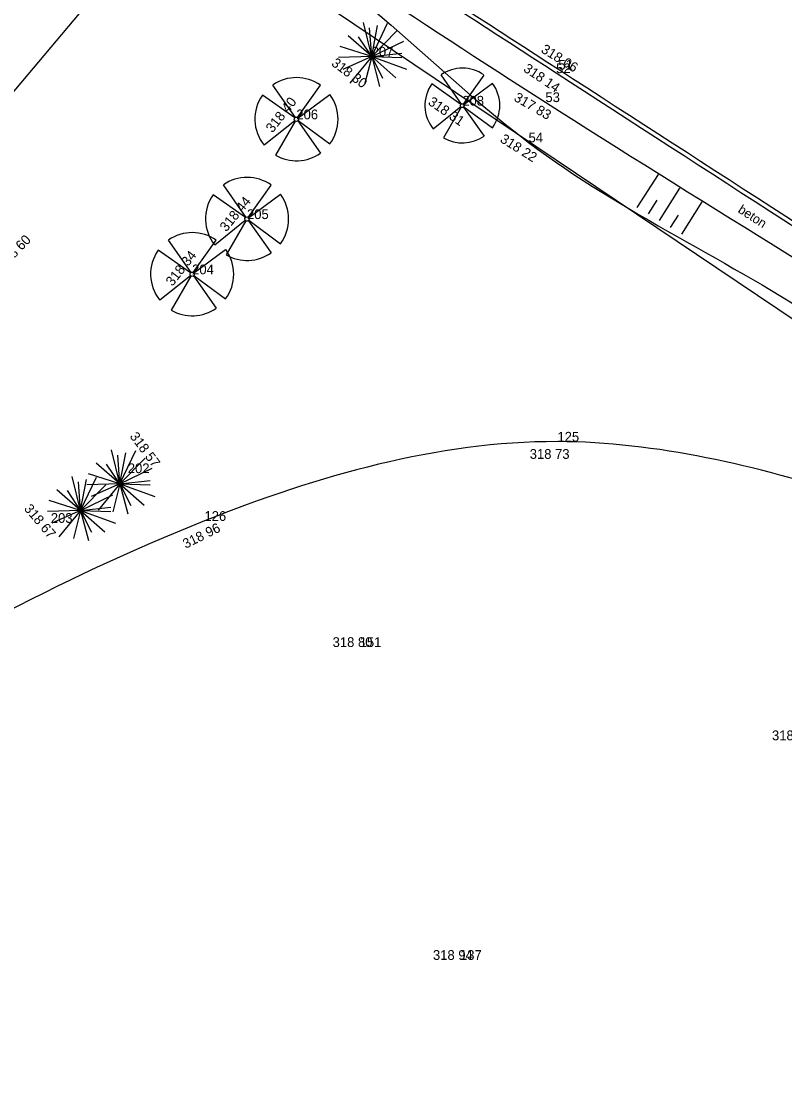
# Model space of a CAD drawing. Extents: x -742884 to -742543, y -1054677 to -1054433.
# Drawn here: x -742729.63 to -742706.11, y -1054520.62 to -1054488.13 of the extents above; entities that cross this region are included whole.
import ezdxf

# ---------------------------------------------------------------- set-up
doc = ezdxf.new("R2010")
doc.units = 0
for name, color, linetype in [('Vrstva 1', 7, 'Continuous'), ('Vrstva 10', 7, 'Continuous'), ('Vrstva 11', 7, 'Continuous'), ('Vrstva 13', 7, 'Continuous'), ('Vrstva 15', 7, 'Continuous'), ('Vrstva 2', 7, 'Continuous'), ('Vrstva 3', 7, 'Continuous'), ('Vrstva 4', 7, 'Continuous'), ('Vrstva 50', 7, 'Continuous')]:
    doc.layers.add(name, color=color, linetype=linetype)

# ---------------------------------------------------------------- blocks, each defined once
blk = doc.blocks.new('Z15')
at = {"layer": 'Vrstva 2'}
for p, q in [((-10, 2), (-8, 6)), ((-10, -2), (-10, 2)), ((-8, 6), (-6, 8)), ((-6, 8), (-2, 10)), ((-2, 10), (2, 10)), ((2, 10), (6, 8)), ((6, 8), (8, 6)), ((8, 6), (10, 2)), ((10, 2), (10, -2)), ((-8, -6), (-10, -2)), ((-6, -8), (-8, -6)), ((-2, -10), (-6, -8)), ((2, -10), (-2, -10)), ((6, -8), (2, -10)), ((8, -6), (6, -8)), ((10, -2), (8, -6))]:
    blk.add_line(p, q, dxfattribs=at)

msp = doc.modelspace()

# ---------------------------------------------------------------- linework, layer by layer
at = {"layer": 'Vrstva 1'}
for p, q in [((-742718.83, -1054489.22), (-742718.83, -1054489.22)), ((-742713.15, -1054489.73), (-742713.15, -1054489.73)), ((-742713.08, -1054489.62), (-742713.08, -1054489.62)), ((-742716.04, -1054490.73), (-742716.04, -1054490.73)), ((-742713.48, -1054490.62), (-742713.48, -1054490.62)), ((-742721.15, -1054491.15), (-742721.15, -1054491.15)), ((-742714, -1054491.86), (-742714, -1054491.86)), ((-742722.67, -1054494.22), (-742722.67, -1054494.22)), ((-742724.36, -1054495.92), (-742724.36, -1054495.92)), ((-742713.11, -1054501.07), (-742713.11, -1054501.07)), ((-742726.34, -1054502.04), (-742726.34, -1054502.04)), ((-742723.98, -1054503.51), (-742723.98, -1054503.51)), ((-742728.71, -1054503.57), (-742728.71, -1054503.57)), ((-742719.2, -1054507.39), (-742719.2, -1054507.39)), ((-742716.11, -1054517.02), (-742716.11, -1054517.02))]:
    msp.add_line(p, q, dxfattribs=at)
at = {"layer": 'Vrstva 10'}
for p, q in [((-742718.83, -1054489.22), (-742719.087, -1054488.17)), ((-742718.83, -1054489.22), (-742718.345, -1054488.195)), ((-742718.83, -1054489.22), (-742718.646, -1054488.264)), ((-742718.83, -1054489.22), (-742719.559, -1054488.58)), ((-742718.83, -1054489.22), (-742718.894, -1054488.336)), ((-742718.83, -1054489.22), (-742718.057, -1054488.429)), ((-742718.83, -1054489.22), (-742719.799, -1054488.913)), ((-742718.83, -1054489.22), (-742719.24, -1054488.609)), ((-742718.83, -1054489.22), (-742717.838, -1054488.741)), ((-742718.83, -1054489.22), (-742719.852, -1054489.246)), ((-742718.83, -1054489.22), (-742719.715, -1054489.613)), ((-742718.83, -1054489.22), (-742719.5, -1054490.034)), ((-742718.83, -1054489.22), (-742719.05, -1054490.079)), ((-742718.834, -1054489.214), (-742718.834, -1054489.214)), ((-742718.83, -1054489.22), (-742717.898, -1054489.114)), ((-742718.83, -1054489.22), (-742718.83, -1054489.22)), ((-742718.83, -1054489.22), (-742718.494, -1054489.884)), ((-742718.83, -1054489.22), (-742717.755, -1054489.609)), ((-742718.83, -1054489.22), (-742717.898, -1054489.248)), ((-742718.83, -1054489.22), (-742718.084, -1054489.873)), ((-742718.83, -1054489.22), (-742718.59, -1054490.142)), ((-742718.83, -1054489.22), (-742718.83, -1054489.22)), ((-742716.067, -1054490.684), (-742716.694, -1054489.78)), ((-742716.006, -1054490.684), (-742715.371, -1054489.788)), ((-742721.18, -1054491.099), (-742721.877, -1054490.095)), ((-742721.113, -1054491.099), (-742720.407, -1054490.103)), ((-742716.084, -1054490.69), (-742716.979, -1054490.06)), ((-742715.996, -1054490.697), (-742715.112, -1054490.042)), ((-742721.199, -1054491.106), (-742722.194, -1054490.406)), ((-742721.102, -1054491.113), (-742720.119, -1054490.386)), ((-742716.086, -1054490.769), (-742716.935, -1054491.451)), ((-742716.075, -1054490.78), (-742716.619, -1054491.723)), ((-742716.001, -1054490.776), (-742715.369, -1054491.667)), ((-742715.991, -1054490.763), (-742715.112, -1054491.412)), ((-742721.096, -1054491.187), (-742720.119, -1054491.908)), ((-742721.201, -1054491.193), (-742722.145, -1054491.951)), ((-742721.189, -1054491.206), (-742721.794, -1054492.254)), ((-742721.107, -1054491.201), (-742720.405, -1054492.191)), ((-742722.7, -1054494.169), (-742723.397, -1054493.165)), ((-742722.633, -1054494.169), (-742721.927, -1054493.173)), ((-742722.622, -1054494.183), (-742721.639, -1054493.456)), ((-742722.719, -1054494.176), (-742723.714, -1054493.476)), ((-742722.721, -1054494.263), (-742723.665, -1054495.021)), ((-742722.709, -1054494.276), (-742723.314, -1054495.324)), ((-742722.627, -1054494.271), (-742721.925, -1054495.261)), ((-742722.616, -1054494.257), (-742721.639, -1054494.978)), ((-742724.39, -1054495.869), (-742725.087, -1054494.865)), ((-742724.323, -1054495.869), (-742723.617, -1054494.873)), ((-742724.409, -1054495.876), (-742725.404, -1054495.176)), ((-742724.312, -1054495.883), (-742723.329, -1054495.156)), ((-742724.411, -1054495.963), (-742725.355, -1054496.721)), ((-742724.399, -1054495.976), (-742725.004, -1054497.024)), ((-742724.317, -1054495.971), (-742723.615, -1054496.961)), ((-742724.306, -1054495.957), (-742723.329, -1054496.678)), ((-742726.582, -1054502.37), (-742726.839, -1054501.32)), ((-742726.582, -1054502.37), (-742726.646, -1054501.486)), ((-742726.582, -1054502.37), (-742726.097, -1054501.345)), ((-742726.582, -1054502.37), (-742726.398, -1054501.414)), ((-742726.582, -1054502.37), (-742725.809, -1054501.579)), ((-742726.582, -1054502.37), (-742727.311, -1054501.73)), ((-742726.582, -1054502.37), (-742726.992, -1054501.759)), ((-742726.582, -1054502.37), (-742725.59, -1054501.891)), ((-742727.792, -1054503.19), (-742728.049, -1054502.14)), ((-742727.792, -1054503.19), (-742727.307, -1054502.165)), ((-742727.792, -1054503.19), (-742727.608, -1054502.234)), ((-742726.582, -1054502.37), (-742727.551, -1054502.063)), ((-742727.792, -1054503.19), (-742728.521, -1054502.55)), ((-742727.792, -1054503.19), (-742727.856, -1054502.306)), ((-742727.792, -1054503.19), (-742727.019, -1054502.399)), ((-742726.582, -1054502.37), (-742727.604, -1054502.396)), ((-742726.582, -1054502.37), (-742727.467, -1054502.763)), ((-742726.582, -1054502.37), (-742727.252, -1054503.184)), ((-742726.582, -1054502.37), (-742726.802, -1054503.229)), ((-742726.586, -1054502.364), (-742726.586, -1054502.364)), ((-742726.582, -1054502.37), (-742725.65, -1054502.264)), ((-742726.582, -1054502.37), (-742726.582, -1054502.37)), ((-742726.582, -1054502.37), (-742726.246, -1054503.034)), ((-742726.582, -1054502.37), (-742725.507, -1054502.759)), ((-742726.582, -1054502.37), (-742725.65, -1054502.398)), ((-742726.582, -1054502.37), (-742725.836, -1054503.023)), ((-742726.582, -1054502.37), (-742726.342, -1054503.292)), ((-742726.582, -1054502.37), (-742726.582, -1054502.37)), ((-742727.792, -1054503.19), (-742728.761, -1054502.883)), ((-742727.792, -1054503.19), (-742728.202, -1054502.579)), ((-742727.792, -1054503.19), (-742726.8, -1054502.711)), ((-742727.792, -1054503.19), (-742728.814, -1054503.216)), ((-742727.792, -1054503.19), (-742728.677, -1054503.583)), ((-742727.792, -1054503.19), (-742728.462, -1054504.004)), ((-742727.792, -1054503.19), (-742728.012, -1054504.049)), ((-742727.796, -1054503.184), (-742727.796, -1054503.184)), ((-742727.792, -1054503.19), (-742726.86, -1054503.084)), ((-742727.792, -1054503.19), (-742727.792, -1054503.19)), ((-742727.792, -1054503.19), (-742727.456, -1054503.854)), ((-742727.792, -1054503.19), (-742726.717, -1054503.579)), ((-742727.792, -1054503.19), (-742726.86, -1054503.218)), ((-742727.792, -1054503.19), (-742727.046, -1054503.843)), ((-742727.792, -1054503.19), (-742727.552, -1054504.112)), ((-742727.792, -1054503.19), (-742727.792, -1054503.19))]:
    msp.add_line(p, q, dxfattribs=at)
for centre, radius, start, end in [((-742721.147, -1054491.146), 1.28, 54.7465, 124.8105), ((-742716.037, -1054490.726), 1.152, 54.7465, 124.8105), ((-742716.038, -1054490.724), 1.152, 144.8767, 218.9336), ((-742716.037, -1054490.726), 1.152, 323.4756, 36.2971), ((-742721.148, -1054491.143), 1.28, 144.8767, 218.9336), ((-742721.147, -1054491.146), 1.28, 323.4756, 36.2971), ((-742716.037, -1054490.726), 1.152, 239.6151, 305.4552), ((-742721.147, -1054491.146), 1.28, 239.6151, 305.4552), ((-742722.667, -1054494.216), 1.28, 54.7465, 124.8105), ((-742722.667, -1054494.216), 1.28, 323.4756, 36.2971), ((-742722.668, -1054494.213), 1.28, 144.8767, 218.9336), ((-742724.357, -1054495.916), 1.28, 54.7465, 124.8105), ((-742724.358, -1054495.913), 1.28, 144.8767, 218.9336), ((-742724.357, -1054495.916), 1.28, 323.4756, 36.2971), ((-742722.667, -1054494.216), 1.28, 239.6151, 305.4552), ((-742724.357, -1054495.916), 1.28, 239.6151, 305.4552)]:
    msp.add_arc(centre, radius, start, end, dxfattribs=at)
at = {"layer": 'Vrstva 11'}
for p, q in [((-742710.013, -1054492.844), (-742710.66, -1054493.862)), ((-742709.97, -1054494.269), (-742709.337, -1054493.267)), ((-742710.053, -1054493.642), (-742710.319, -1054494.063)), ((-742709.276, -1054494.681), (-742708.649, -1054493.695)), ((-742709.624, -1054494.475), (-742709.385, -1054494.099))]:
    msp.add_line(p, q, dxfattribs=at)
for points in [[(-742777.63, -1054542.12), (-742764.61, -1054526.83), (-742751.7, -1054511.56), (-742738.47, -1054495.82), (-742727.02, -1054482.18), (-742726.38, -1054482.19), (-742725.15, -1054482.94)], [(-742776.7, -1054542.68), (-742764.01, -1054527.79), (-742751.11, -1054512.75), (-742737.61, -1054496.47), (-742726.42, -1054483.98), (-742725.9, -1054484.03), (-742714, -1054491.86), (-742704.819, -1054497.481), (-742700.94, -1054500.269), (-742696.44, -1054503.39), (-742688.83, -1054509.5), (-742682.54, -1054514.17), (-742675.15, -1054519.77), (-742673.01, -1054522.11), (-742671.05, -1054524.7)], [(-742641.45, -1054542), (-742646.08, -1054542.32), (-742650.28, -1054545.1), (-742653.63, -1054549.14), (-742658.66, -1054557.13), (-742664.13, -1054565.84), (-742667.81, -1054569.62), (-742669.76, -1054570.07), (-742674.4, -1054567.88), (-742684.66, -1054562.03), (-742693.02, -1054556.88), (-742694.43, -1054554.37), (-742693.99, -1054552.67), (-742684.52, -1054539.64), (-742677.51, -1054529.95), (-742676.26, -1054526.54), (-742677.27, -1054522.39), (-742681.19, -1054517.29), (-742689.28, -1054510.73), (-742697.86, -1054505.14), (-742704.02, -1054502.75), (-742713.11, -1054501.07), (-742723.98, -1054503.51), (-742736.77, -1054510.1), (-742745.39, -1054515.75), (-742752.81, -1054521.82), (-742762.72, -1054531.38), (-742770.54, -1054539.36), (-742775.54, -1054544.64)]]:
    msp.add_spline(points, degree=3, dxfattribs=at)
at = {"layer": 'Vrstva 13'}
msp.add_spline([(-742725.15, -1054482.94), (-742713.48, -1054490.62), (-742699.44, -1054499.41), (-742696.97, -1054500.991)], degree=3, dxfattribs=at)
at = {"layer": 'Vrstva 4'}
for points in [[(-742783.23, -1054536.93), (-742770.7, -1054522.44), (-742757.28, -1054506.67), (-742744.15, -1054491.3), (-742731.95, -1054477.03), (-742724.73, -1054468.59)], [(-742718.8, -1054478.84), (-742709.4, -1054484.88), (-742695.99, -1054493.43), (-742680.4, -1054503.55), (-742661.01, -1054516), (-742635.78, -1054532.31)], [(-742778.49, -1054541.37), (-742765.63, -1054526.43), (-742752.39, -1054510.77), (-742739.19, -1054495.37), (-742727.3, -1054481.14)], [(-742668.427, -1054518.574), (-742683.74, -1054508.68), (-742696.59, -1054500.4), (-742699.13, -1054498.77), (-742713.15, -1054489.73), (-742724.623, -1054482.289)], [(-742668.31, -1054518.5), (-742683.67, -1054508.57), (-742699.06, -1054498.66), (-742713.08, -1054489.62), (-742724.57, -1054482.17)]]:
    msp.add_spline(points, degree=3, dxfattribs=at)
at = {"layer": 'Vrstva 50'}
for points in [[(-742724.95, -1054484.46), (-742747.39, -1054511.11), (-742766.3, -1054533.47), (-742786.45, -1054556.28), (-742796.57, -1054568.72)], [(-742724.95, -1054484.46), (-742672.19, -1054519.91), (-742671.42, -1054521.73), (-742671.38, -1054524.18), (-742670.45, -1054526.06)]]:
    msp.add_lwpolyline(points, dxfattribs=at)

# ---------------------------------------------------------------- block references
at = {"layer": 'Vrstva 10', "rotation": -30.671756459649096}
for p, xscale, yscale in [((-742716.04, -1054490.73), 0.00575829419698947, 0.005758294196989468), ((-742721.15, -1054491.15), 0.006398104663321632, 0.006398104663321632), ((-742722.67, -1054494.22), 0.006398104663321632, 0.006398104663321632), ((-742724.36, -1054495.92), 0.006398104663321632, 0.006398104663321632)]:
    msp.add_blockref('Z15', p, dxfattribs=dict(at, xscale=xscale, yscale=yscale))

# ---------------------------------------------------------------- texts
at = {"layer": 'Vrstva 15'}
msp.add_text('beton', height=0.2816, rotation=327.2766, dxfattribs=at).set_placement((-742707.574, -1054493.997))
at = {"layer": 'Vrstva 2'}
for s, p in [('207', (-742718.83, -1054489.22)), ('52', (-742713.15, -1054489.73)), ('51', (-742713.08, -1054489.62)), ('208', (-742716.04, -1054490.73)), ('53', (-742713.48, -1054490.62)), ('206', (-742721.15, -1054491.15)), ('54', (-742714, -1054491.86)), ('205', (-742722.67, -1054494.22)), ('204', (-742724.36, -1054495.92)), ('125', (-742713.11, -1054501.07)), ('202', (-742726.34, -1054502.04)), ('126', (-742723.98, -1054503.51)), ('203', (-742728.71, -1054503.57)), ('151', (-742719.2, -1054507.39)), ('137', (-742716.11, -1054517.02))]:
    msp.add_text(s, height=0.3, dxfattribs=at).set_placement(p)
at = {"layer": 'Vrstva 3'}
for s, rotation, p in [('318 06 ', 328.1947, (-742713.639, -1054489.072)), ('318 30 ', 323.2356, (-742720.094, -1054489.474)), ('318 14 ', 326.0972, (-742714.181, -1054489.656)), ('318 40 ', 51.7856, (-742721.883, -1054491.583)), ('318 31 ', 325.5735, (-742717.117, -1054490.677)), ('317 83 ', 329.8516, (-742714.475, -1054490.562)), ('318 22 ', 327.8628, (-742714.899, -1054491.831)), ('318 44 ', 50.6106, (-742723.306, -1054494.63)), ('318 60 ', 46.2075, (-742730.15, -1054495.767)), ('318 34 ', 51.8329, (-742724.964, -1054496.307)), ('318 57 ', 306.9079, (-742726.294, -1054500.912)), ('318 67 ', 310.2491, (-742729.552, -1054503.144)), ('318 96 ', 26.4379, (-742724.556, -1054504.37))]:
    msp.add_text(s, height=0.3, rotation=rotation, dxfattribs=at).set_placement(p)
for s, p in [('318 73 ', (-742713.963, -1054501.6)), ('318 80 ', (-742720.033, -1054507.39)), ('318 71 ', (-742706.503, -1054510.26)), ('318 94 ', (-742716.943, -1054517.02))]:
    msp.add_text(s, height=0.3, dxfattribs=at).set_placement(p)

doc.saveas('drawing.dxf')
